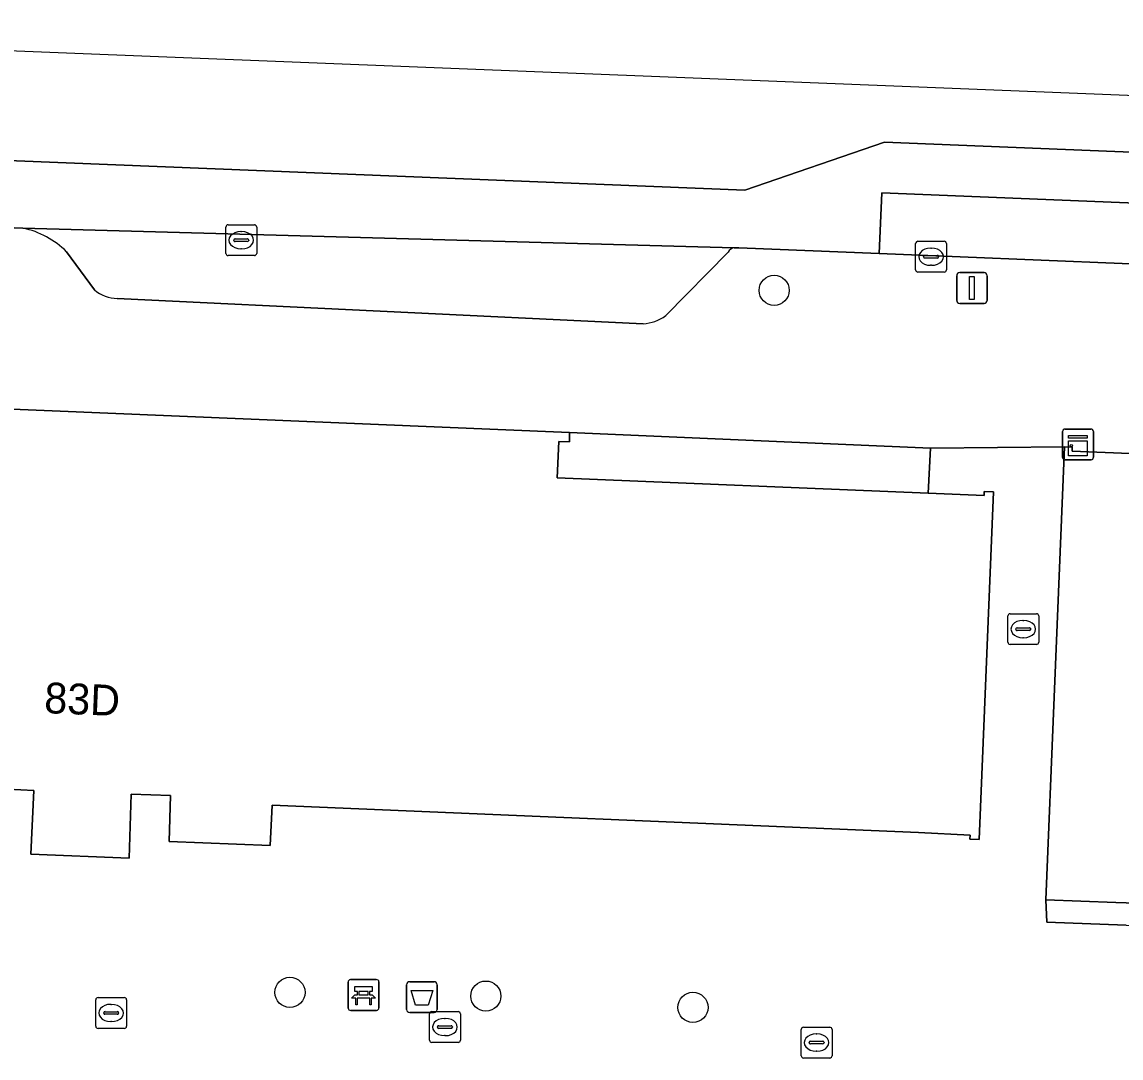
# Model space of a CAD drawing. Extents: x 160888 to 161385, y 386490 to 386908.
# Drawn here: x 161012.2 to 161047.88, y 386874.17 to 386907.8 of the extents above; entities that cross this region are included whole.
import ezdxf

# ---------------------------------------------------------------- set-up
doc = ezdxf.new("R2010")
doc.units = 0
for name, color, linetype in [('IMGEO_Afvalbak', 7, 'Continuous'), ('IMGEO_Bank', 7, 'Continuous'), ('IMGEO_Boom', 7, 'Continuous'), ('IMGEO_Kast', 7, 'Continuous'), ('IMGEO_Kolk', 7, 'Continuous'), ('IMGEO_Lichtmast', 7, 'Continuous'), ('IMGEO_Pand', 7, 'Continuous'), ('IMGEO_Pand_nummerreeks', 7, 'Continuous'), ('IMGEO_Parkeervlak_gesloten', 7, 'Continuous'), ('IMGEO_Parkeervlak_open', 7, 'Continuous'), ('IMGEO_Rijbaan_lokaal_gesloten', 7, 'Continuous'), ('IMGEO_Voetpad_open', 7, 'Continuous')]:
    doc.layers.add(name, color=color, linetype=linetype)

msp = doc.modelspace()

# ---------------------------------------------------------------- linework, layer by layer
at = {"layer": 'IMGEO_Afvalbak'}
for p, q in [((161024.689, 386875.746), (161024.689, 386876.546)), ((161024.689, 386876.546), (161024.689, 386875.746)), ((161024.789, 386876.646), (161025.579, 386876.646)), ((161025.579, 386876.646), (161024.789, 386876.646)), ((161025.679, 386876.546), (161025.679, 386875.746)), ((161025.679, 386875.746), (161025.679, 386876.546)), ((161025.579, 386875.646), (161024.789, 386875.646)), ((161024.789, 386875.646), (161025.579, 386875.646))]:
    msp.add_line(p, q, dxfattribs=at)
msp.add_lwpolyline([(161024.832, 386876.36), (161025.536, 386876.36), (161025.387, 386875.89), (161024.981, 386875.89), (161024.832, 386876.36)], dxfattribs=at)
for centre, start, end in [((161024.789, 386876.546), 90, 180), ((161024.789, 386876.546), 90, 180), ((161025.579, 386876.546), 0, 90), ((161025.579, 386876.546), 360, 90), ((161024.789, 386875.746), 180, 270), ((161024.789, 386875.746), 180, 270), ((161025.579, 386875.746), 270, 0), ((161025.579, 386875.746), 270, 0)]:
    msp.add_arc(centre, 0.1, start, end, dxfattribs=at)
at = {"layer": 'IMGEO_Bank'}
for p, q in [((161022.79, 386875.792), (161022.79, 386876.633)), ((161022.79, 386876.633), (161022.79, 386875.792)), ((161022.865, 386876.717), (161023.706, 386876.717)), ((161023.706, 386876.717), (161022.865, 386876.717)), ((161023.79, 386876.642), (161023.79, 386875.801)), ((161023.79, 386875.801), (161023.79, 386876.642)), ((161023.099, 386876.223), (161023.099, 386876.329)), ((161023.143, 386876.329), (161023.143, 386876.223)), ((161023.431, 386876.335), (161023.149, 386876.335)), ((161023.149, 386876.217), (161023.431, 386876.217)), ((161023.437, 386876.223), (161023.437, 386876.329)), ((161023.481, 386876.329), (161023.481, 386876.223)), ((161023.487, 386876.115), (161023.094, 386876.115)), ((161023.715, 386875.717), (161022.874, 386875.717)), ((161022.874, 386875.717), (161023.715, 386875.717))]:
    msp.add_line(p, q, dxfattribs=at)
for points in [[(161023.093, 386876.335), (161023.007, 386876.335), (161023.007, 386876.496), (161023.57, 386876.496), (161023.57, 386876.335), (161023.487, 386876.335)], [(161023.037, 386876.115), (161022.895, 386876.115), (161023.007, 386876.217), (161023.093, 386876.217)], [(161023.487, 386876.217), (161023.57, 386876.217), (161023.682, 386876.115), (161023.543, 386876.115)], [(161023.087, 386876.108), (161023.087, 386875.901), (161023.044, 386875.901), (161023.044, 386876.108)], [(161023.537, 386876.108), (161023.537, 386875.901), (161023.493, 386875.901), (161023.493, 386876.108)]]:
    msp.add_lwpolyline(points, dxfattribs=at)
for centre, radius, start, end in [((161022.868, 386876.639), 0.0779, 92.4484, 184.2845), ((161022.868, 386876.639), 0.0779, 92.4484, 184.2845), ((161023.712, 386876.639), 0.0779, 2.4484, 94.2845), ((161023.712, 386876.639), 0.0779, 2.4484, 94.2845), ((161023.092, 386876.328), 0.00671, 2.8957, 87.1043), ((161023.092, 386876.224), 0.00671, 272.8957, 357.1043), ((161023.149, 386876.328), 0.00671, 92.8957, 177.1043), ((161023.149, 386876.224), 0.00671, 182.8957, 267.1043), ((161023.431, 386876.328), 0.00671, 2.8957, 87.1043), ((161023.431, 386876.224), 0.00671, 272.8957, 357.1043), ((161023.488, 386876.328), 0.00671, 92.8957, 177.1043), ((161023.488, 386876.224), 0.00671, 182.8957, 267.1043), ((161022.868, 386875.795), 0.0779, 182.4484, 274.2845), ((161022.868, 386875.795), 0.0779, 182.4484, 274.2845), ((161023.037, 386876.108), 0.00671, 2.8957, 87.1043), ((161023.094, 386876.108), 0.00671, 92.8957, 177.1043), ((161023.486, 386876.108), 0.00671, 2.8957, 87.1043), ((161023.543, 386876.108), 0.00671, 92.8957, 177.1043), ((161023.712, 386875.795), 0.0779, 272.4484, 4.2845), ((161023.712, 386875.795), 0.0779, 272.4484, 4.2845)]:
    msp.add_arc(centre, radius, start, end, dxfattribs=at)
at = {"layer": 'IMGEO_Boom'}
for centre in [(161036.621, 386899.089), (161020.902, 386876.302), (161027.261, 386876.181), (161033.985, 386875.814)]:
    msp.add_circle(centre, 0.489, dxfattribs=at)
at = {"layer": 'IMGEO_Kast'}
for p, q in [((161045.986, 386893.662), (161045.986, 386894.503)), ((161045.986, 386894.503), (161045.986, 386893.662)), ((161046.061, 386894.587), (161046.902, 386894.587)), ((161046.902, 386894.587), (161046.061, 386894.587)), ((161046.986, 386894.512), (161046.986, 386893.671)), ((161046.986, 386893.671), (161046.986, 386894.512)), ((161046.911, 386893.587), (161046.07, 386893.587)), ((161046.07, 386893.587), (161046.911, 386893.587))]:
    msp.add_line(p, q, dxfattribs=at)
for points in [[(161046.181, 386894.377), (161046.781, 386894.377), (161046.781, 386894.292), (161046.181, 386894.292), (161046.181, 386894.377)], [(161046.181, 386894.202), (161046.781, 386894.202), (161046.781, 386893.713), (161046.181, 386893.713), (161046.181, 386894.202)]]:
    msp.add_lwpolyline(points, dxfattribs=at)
msp.add_circle((161046.265, 386894.051), 0.0377, dxfattribs=at)
for centre, start, end in [((161046.064, 386894.509), 92.4484, 184.2845), ((161046.064, 386894.509), 92.4484, 184.2845), ((161046.908, 386894.509), 2.4484, 94.2845), ((161046.908, 386894.509), 2.4484, 94.2845), ((161046.064, 386893.665), 182.4484, 274.2845), ((161046.064, 386893.665), 182.4484, 274.2845), ((161046.908, 386893.665), 272.4484, 4.2845), ((161046.908, 386893.665), 272.4484, 4.2845)]:
    msp.add_arc(centre, 0.0779, start, end, dxfattribs=at)
at = {"layer": 'IMGEO_Kolk'}
for p, q in [((161018.821, 386900.29), (161018.821, 386901.142)), ((161018.896, 386901.216), (161019.748, 386901.216)), ((161019.822, 386901.142), (161019.822, 386900.29)), ((161019.123, 386900.759), (161019.521, 386900.759)), ((161019.309, 386900.996), (161019.334, 386900.996)), ((161019.08, 386900.71), (161019.08, 386900.722)), ((161019.518, 386900.673), (161019.12, 386900.673)), ((161019.332, 386900.436), (161019.307, 386900.436)), ((161019.564, 386900.722), (161019.564, 386900.71)), ((161041.214, 386899.755), (161041.214, 386900.607)), ((161041.289, 386900.681), (161042.141, 386900.681)), ((161041.702, 386900.461), (161041.727, 386900.461)), ((161042.215, 386900.607), (161042.215, 386899.755)), ((161019.748, 386900.216), (161018.896, 386900.216)), ((161041.473, 386900.175), (161041.473, 386900.187)), ((161041.911, 386900.138), (161041.513, 386900.138)), ((161041.516, 386900.224), (161041.914, 386900.224)), ((161041.957, 386900.187), (161041.957, 386900.175)), ((161041.725, 386899.901), (161041.7, 386899.901)), ((161042.141, 386899.681), (161041.289, 386899.681)), ((161044.208, 386887.667), (161044.208, 386888.519)), ((161044.283, 386888.593), (161045.135, 386888.593)), ((161044.696, 386888.373), (161044.721, 386888.373)), ((161045.209, 386888.519), (161045.209, 386887.667)), ((161044.467, 386888.087), (161044.467, 386888.099)), ((161044.905, 386888.05), (161044.507, 386888.05)), ((161044.51, 386888.136), (161044.908, 386888.136)), ((161044.951, 386888.099), (161044.951, 386888.087)), ((161045.135, 386887.593), (161044.283, 386887.593)), ((161044.719, 386887.813), (161044.694, 386887.813)), ((161014.597, 386875.206), (161014.597, 386876.058)), ((161014.672, 386876.132), (161015.524, 386876.132)), ((161015.085, 386875.912), (161015.11, 386875.912)), ((161015.598, 386876.058), (161015.598, 386875.206)), ((161014.856, 386875.626), (161014.856, 386875.638)), ((161015.294, 386875.589), (161014.896, 386875.589)), ((161014.899, 386875.675), (161015.297, 386875.675)), ((161015.34, 386875.638), (161015.34, 386875.626)), ((161025.433, 386874.751), (161025.433, 386875.603)), ((161025.508, 386875.677), (161026.36, 386875.677)), ((161025.921, 386875.457), (161025.946, 386875.457)), ((161026.434, 386875.603), (161026.434, 386874.751)), ((161015.524, 386875.132), (161014.672, 386875.132)), ((161015.108, 386875.352), (161015.083, 386875.352)), ((161025.692, 386875.171), (161025.692, 386875.183)), ((161026.13, 386875.134), (161025.732, 386875.134)), ((161025.735, 386875.22), (161026.133, 386875.22)), ((161026.176, 386875.183), (161026.176, 386875.171)), ((161037.498, 386874.245), (161037.498, 386875.097)), ((161037.573, 386875.171), (161038.425, 386875.171)), ((161038.499, 386875.097), (161038.499, 386874.245)), ((161025.944, 386874.897), (161025.919, 386874.897)), ((161037.8, 386874.714), (161038.198, 386874.714)), ((161037.986, 386874.951), (161038.011, 386874.951)), ((161026.36, 386874.677), (161025.508, 386874.677)), ((161037.757, 386874.665), (161037.757, 386874.677)), ((161038.195, 386874.628), (161037.797, 386874.628)), ((161038.009, 386874.391), (161037.984, 386874.391)), ((161038.241, 386874.677), (161038.241, 386874.665)), ((161038.425, 386874.171), (161037.573, 386874.171))]:
    msp.add_line(p, q, dxfattribs=at)
for points in [[(161018.821, 386900.29), (161018.821, 386901.142)], [(161018.896, 386901.216), (161019.748, 386901.216)], [(161019.822, 386901.142), (161019.822, 386900.29)], [(161041.214, 386899.755), (161041.214, 386900.607)], [(161041.289, 386900.681), (161042.141, 386900.681)], [(161042.215, 386900.607), (161042.215, 386899.755)], [(161019.748, 386900.216), (161018.896, 386900.216)], [(161042.141, 386899.681), (161041.289, 386899.681)], [(161044.208, 386887.667), (161044.208, 386888.519)], [(161044.283, 386888.593), (161045.135, 386888.593)], [(161045.209, 386888.519), (161045.209, 386887.667)], [(161045.135, 386887.593), (161044.283, 386887.593)], [(161014.597, 386875.206), (161014.597, 386876.058)], [(161014.672, 386876.132), (161015.524, 386876.132)], [(161015.598, 386876.058), (161015.598, 386875.206)], [(161025.433, 386874.751), (161025.433, 386875.603)], [(161025.508, 386875.677), (161026.36, 386875.677)], [(161026.434, 386875.603), (161026.434, 386874.751)], [(161015.524, 386875.132), (161014.672, 386875.132)], [(161037.498, 386874.245), (161037.498, 386875.097)], [(161037.573, 386875.171), (161038.425, 386875.171)], [(161038.499, 386875.097), (161038.499, 386874.245)], [(161026.36, 386874.677), (161025.508, 386874.677)], [(161038.425, 386874.171), (161037.573, 386874.171)]]:
    msp.add_lwpolyline(points, dxfattribs=at)
for centre, radius, start, end in [((161018.898, 386901.14), 0.0765, 91.552, 178.448), ((161018.898, 386901.14), 0.0765, 91.552, 178.448), ((161019.746, 386901.14), 0.0765, 1.552, 88.448), ((161019.746, 386901.14), 0.0765, 1.552, 88.448), ((161019.12, 386900.719), 0.0403, 85.8775, 175.7526), ((161019.525, 386900.721), 0.0386, 1.7309, 96.639), ((161019.117, 386900.709), 0.0366, 178.938, 274.7102), ((161019.521, 386900.716), 0.043, 264.8664, 352.4533), ((161041.291, 386900.605), 0.0765, 91.552, 178.448), ((161041.291, 386900.605), 0.0765, 91.552, 178.448), ((161042.139, 386900.605), 0.0765, 1.552, 88.448), ((161042.139, 386900.605), 0.0765, 1.552, 88.448), ((161018.898, 386900.292), 0.0765, 181.552, 268.448), ((161018.898, 386900.292), 0.0765, 181.552, 268.448), ((161019.746, 386900.292), 0.0765, 271.552, 358.448), ((161019.746, 386900.292), 0.0765, 271.552, 358.448), ((161041.513, 386900.184), 0.0403, 85.8775, 175.7526), ((161041.51, 386900.174), 0.0366, 178.938, 274.7102), ((161041.914, 386900.181), 0.043, 264.8664, 352.4533), ((161041.918, 386900.186), 0.0386, 1.7309, 96.639), ((161041.291, 386899.757), 0.0765, 181.552, 268.448), ((161041.291, 386899.757), 0.0765, 181.552, 268.448), ((161042.139, 386899.757), 0.0765, 271.552, 358.448), ((161042.139, 386899.757), 0.0765, 271.552, 358.448), ((161044.285, 386888.517), 0.0765, 91.552, 178.448), ((161044.285, 386888.517), 0.0765, 91.552, 178.448), ((161045.133, 386888.517), 0.0765, 1.552, 88.448), ((161045.133, 386888.517), 0.0765, 1.552, 88.448), ((161044.507, 386888.096), 0.0403, 85.8775, 175.7526), ((161044.504, 386888.086), 0.0366, 178.938, 274.7102), ((161044.908, 386888.093), 0.043, 264.8664, 352.4533), ((161044.912, 386888.098), 0.0386, 1.7309, 96.639), ((161044.285, 386887.669), 0.0765, 181.552, 268.448), ((161044.285, 386887.669), 0.0765, 181.552, 268.448), ((161045.133, 386887.669), 0.0765, 271.552, 358.448), ((161045.133, 386887.669), 0.0765, 271.552, 358.448), ((161014.674, 386876.056), 0.0765, 91.552, 178.448), ((161014.674, 386876.056), 0.0765, 91.552, 178.448), ((161015.522, 386876.056), 0.0765, 1.552, 88.448), ((161015.522, 386876.056), 0.0765, 1.552, 88.448), ((161014.896, 386875.635), 0.0403, 85.8775, 175.7526), ((161014.893, 386875.625), 0.0366, 178.938, 274.7102), ((161015.297, 386875.632), 0.043, 264.8664, 352.4533), ((161015.301, 386875.637), 0.0386, 1.7309, 96.639), ((161025.51, 386875.601), 0.0765, 91.552, 178.448), ((161025.51, 386875.601), 0.0765, 91.552, 178.448), ((161026.358, 386875.601), 0.0765, 1.552, 88.448), ((161026.358, 386875.601), 0.0765, 1.552, 88.448), ((161014.674, 386875.208), 0.0765, 181.552, 268.448), ((161014.674, 386875.208), 0.0765, 181.552, 268.448), ((161015.522, 386875.208), 0.0765, 271.552, 358.448), ((161015.522, 386875.208), 0.0765, 271.552, 358.448), ((161025.732, 386875.18), 0.0403, 85.8775, 175.7526), ((161025.729, 386875.17), 0.0366, 178.938, 274.7102), ((161026.133, 386875.177), 0.043, 264.8664, 352.4533), ((161026.137, 386875.182), 0.0386, 1.7309, 96.639), ((161037.575, 386875.095), 0.0765, 91.552, 178.448), ((161037.575, 386875.095), 0.0765, 91.552, 178.448), ((161038.423, 386875.095), 0.0765, 1.552, 88.448), ((161038.423, 386875.095), 0.0765, 1.552, 88.448), ((161025.51, 386874.753), 0.0765, 181.552, 268.448), ((161025.51, 386874.753), 0.0765, 181.552, 268.448), ((161026.358, 386874.753), 0.0765, 271.552, 358.448), ((161026.358, 386874.753), 0.0765, 271.552, 358.448), ((161037.797, 386874.674), 0.0403, 85.8775, 175.7526), ((161038.202, 386874.676), 0.0386, 1.7309, 96.639), ((161037.794, 386874.664), 0.0366, 178.938, 274.7102), ((161038.198, 386874.671), 0.043, 264.8664, 352.4533), ((161037.575, 386874.247), 0.0765, 181.552, 268.448), ((161037.575, 386874.247), 0.0765, 181.552, 268.448), ((161038.423, 386874.247), 0.0765, 271.552, 358.448), ((161038.423, 386874.247), 0.0765, 271.552, 358.448)]:
    msp.add_arc(centre, radius, start, end, dxfattribs=at)
for centre, major_axis, ratio, start_param, end_param in [((161019.308, 386900.716), (-0.387, 0.002), 0.722429, 4.712389, 7.853982), ((161019.333, 386900.716), (-0.39, 0.002), 0.717154, 1.570796, 4.712389), ((161041.701, 386900.181), (-0.387, 0.002), 0.722429, 4.712389, 7.853982), ((161041.726, 386900.181), (-0.39, 0.002), 0.717154, 1.570796, 4.712389), ((161044.695, 386888.093), (-0.387, 0.002), 0.722429, 4.712389, 7.853982), ((161044.72, 386888.093), (-0.39, 0.002), 0.717154, 1.570796, 4.712389), ((161015.084, 386875.632), (-0.387, 0.002), 0.722429, 4.712389, 7.853982), ((161015.109, 386875.632), (-0.39, 0.002), 0.717154, 1.570796, 4.712389), ((161025.92, 386875.177), (-0.387, 0.002), 0.722429, 4.712389, 7.853982), ((161025.945, 386875.177), (-0.39, 0.002), 0.717154, 1.570796, 4.712389), ((161037.985, 386874.671), (-0.387, 0.002), 0.722429, 4.712389, 7.853982), ((161038.01, 386874.671), (-0.39, 0.002), 0.717154, 1.570796, 4.712389)]:
    msp.add_ellipse(centre, major_axis=major_axis, ratio=ratio, start_param=start_param, end_param=end_param, dxfattribs=at)
at = {"layer": 'IMGEO_Lichtmast'}
for p, q in [((161042.546, 386898.764), (161042.546, 386899.564)), ((161042.546, 386899.564), (161042.546, 386898.764)), ((161042.646, 386899.664), (161043.436, 386899.664)), ((161043.436, 386899.664), (161042.646, 386899.664)), ((161043.536, 386899.564), (161043.536, 386898.764)), ((161043.536, 386898.764), (161043.536, 386899.564)), ((161043.436, 386898.664), (161042.646, 386898.664)), ((161042.646, 386898.664), (161043.436, 386898.664))]:
    msp.add_line(p, q, dxfattribs=at)
msp.add_lwpolyline([(161042.966, 386899.539), (161043.116, 386899.539), (161043.116, 386898.789), (161042.966, 386898.789), (161042.966, 386899.539)], dxfattribs=at)
for centre, start, end in [((161042.646, 386899.564), 90, 180), ((161042.646, 386899.564), 90, 180), ((161043.436, 386899.564), 0, 90), ((161043.436, 386899.564), 360, 90), ((161042.646, 386898.764), 180, 270), ((161042.646, 386898.764), 180, 270), ((161043.436, 386898.764), 270, 0), ((161043.436, 386898.764), 270, 0)]:
    msp.add_arc(centre, 0.1, start, end, dxfattribs=at)
at = {"layer": 'IMGEO_Pand'}
msp.add_lwpolyline([(161011.314, 386882.915), (161012.587, 386882.859), (161012.496, 386880.789), (161015.686, 386880.661), (161015.75, 386882.733), (161017.026, 386882.693), (161016.978, 386881.201), (161020.255, 386881.065), (161020.328, 386882.383), (161041.31, 386881.494), (161042.983, 386881.409), (161042.977, 386881.279), (161043.277, 386881.267), (161043.741, 386892.544), (161043.44, 386892.556), (161043.434, 386892.427), (161041.618, 386892.502), (161029.577, 386892.999), (161029.633, 386894.185), (161029.973, 386894.176), (161029.981, 386894.476), (161004.65, 386895.537)], dxfattribs=at)
msp.add_lwpolyline([(161113.143, 386891.17), (161097.194, 386891.813), (161080.645, 386892.481), (161055.667, 386893.489), (161046.293, 386893.867), (161046.299, 386893.997), (161046.043, 386894.008), (161045.711, 386885.882), (161045.442, 386879.308), (161047.716, 386879.222), (161049.049, 386879.172), (161064.569, 386878.588), (161069.116, 386878.417), (161073.594, 386878.249), (161112.563, 386876.783), (161112.919, 386885.615)], close=True, dxfattribs=at)
at = {"layer": 'IMGEO_Parkeervlak_gesloten'}
msp.add_lwpolyline([(161064.059, 386901.284), (161040.12, 386902.25), (161040.028, 386900.281), (161063.696, 386899.307), (161064.015, 386899.299)], close=True, dxfattribs=at)
at = {"layer": 'IMGEO_Parkeervlak_open'}
for points in [[(161035.324, 386900.473), (161012.233, 386901.108)], [(161013.653, 386900.34), (161014.554, 386899.103)], [(161033.101, 386898.269), (161035.124, 386900.328)], [(161015.294, 386898.823), (161032.364, 386898.006)]]:
    msp.add_lwpolyline(points, dxfattribs=at)
for centre, radius, start, end in [((161011.649, 386898.331), 2.837, 45.0654, 78.1215), ((161035.393, 386900.168), 0.313, 102.7, 149.1842), ((161015.337, 386900.055), 1.233, 230.5588, 267.99), ((161032.311, 386899.318), 1.313, 272.3016, 306.9765)]:
    msp.add_arc(centre, radius, start, end, dxfattribs=at)
at = {"layer": 'IMGEO_Rijbaan_lokaal_gesloten'}
for points in [[(161112.38, 386902.848), (160988.148, 386907.8), (160987.595, 386907.148)], [(160986.431, 386905.776), (160986.431, 386905.776), (160987.414, 386904.997), (160988.842, 386904.061), (160989.598, 386903.645), (160992.187, 386902.648), (160994.092, 386902.091), (160996.449, 386901.746), (160999.189, 386901.61), (161000, 386901.579), (161012.233, 386901.108), (161035.324, 386900.473), (161035.479, 386900.468), (161040.028, 386900.281), (161040.12, 386902.25), (161064.059, 386901.284), (161073.486, 386900.908), (161109.397, 386899.476), (161112.234, 386899.353), (161112.299, 386900.982), (161040.205, 386903.901), (161035.665, 386902.345), (160996.157, 386903.935)], [(160996.157, 386903.935), (161035.665, 386902.345), (161040.205, 386903.901), (161112.299, 386900.982), (161112.38, 386902.848)]]:
    msp.add_lwpolyline(points, dxfattribs=at)
at = {"layer": 'IMGEO_Voetpad_open'}
for points in [[(161012.233, 386901.108), (161000, 386901.579), (160999.189, 386901.61), (160996.449, 386901.746), (160994.092, 386902.091), (160993.843, 386900.994), (160991.464, 386901.654), (160989.828, 386902.333), (160989.598, 386903.645)], [(160986.001, 386902.936), (160981.133, 386897.248), (160982.853, 386895.847), (160984.295, 386894.643), (160993.236, 386896.016), (161004.65, 386895.537), (161029.981, 386894.476), (161035.955, 386894.217), (161041.701, 386893.968), (161046.043, 386894.008), (161046.299, 386893.997), (161046.293, 386893.867), (161055.667, 386893.489), (161080.645, 386892.481), (161097.194, 386891.813), (161113.143, 386891.17), (161127.058, 386890.969), (161178.427, 386888.94)], [(161109.361, 386897.456), (161109.298, 386897.46), (161108.628, 386897.506), (161074.03, 386898.891), (161073.403, 386898.925), (161071.838, 386899.01), (161071.724, 386897.893), (161068.662, 386898.016), (161065.732, 386898.135), (161065.827, 386899.252), (161064.015, 386899.299), (161063.696, 386899.307), (161040.028, 386900.281), (161035.479, 386900.468), (161035.324, 386900.473)], [(161014.554, 386899.103), (161013.653, 386900.34)], [(161035.124, 386900.328), (161033.101, 386898.269)], [(161032.364, 386898.006), (161015.294, 386898.823)], [(161048.048, 386878.482), (161045.473, 386878.577), (161045.442, 386879.308), (161045.711, 386885.882), (161046.043, 386894.008), (161041.701, 386893.968), (161041.618, 386892.502), (161043.434, 386892.427), (161043.44, 386892.556), (161043.741, 386892.544), (161043.277, 386881.267), (161042.977, 386881.279), (161042.983, 386881.409), (161041.31, 386881.494), (161020.328, 386882.383), (161020.255, 386881.065), (161016.978, 386881.201), (161017.026, 386882.693), (161015.75, 386882.733), (161015.686, 386880.661), (161012.496, 386880.789), (161012.587, 386882.859), (161011.314, 386882.915)]]:
    msp.add_lwpolyline(points, dxfattribs=at)
for points in [[(161041.701, 386893.968), (161035.955, 386894.217), (161029.981, 386894.476), (161029.973, 386894.176), (161029.633, 386894.185), (161029.577, 386892.999), (161041.618, 386892.502)], [(161045.473, 386878.577), (161048.048, 386878.482), (161049.023, 386878.446), (161049.049, 386879.172), (161047.716, 386879.222), (161045.442, 386879.308)]]:
    msp.add_lwpolyline(points, close=True, dxfattribs=at)
for centre, radius, start, end in [((161011.649, 386898.331), 2.837, 45.0654, 78.1215), ((161035.393, 386900.168), 0.313, 102.7, 149.1842), ((161015.337, 386900.055), 1.233, 230.5588, 267.99), ((161032.311, 386899.318), 1.313, 272.3016, 306.9765)]:
    msp.add_arc(centre, radius, start, end, dxfattribs=at)

# ---------------------------------------------------------------- texts
at = {"layer": 'IMGEO_Pand_nummerreeks'}
msp.add_text('83D', height=1, rotation=357.7188, dxfattribs=at).set_placement((161012.914, 386885.368))

doc.saveas('drawing.dxf')
